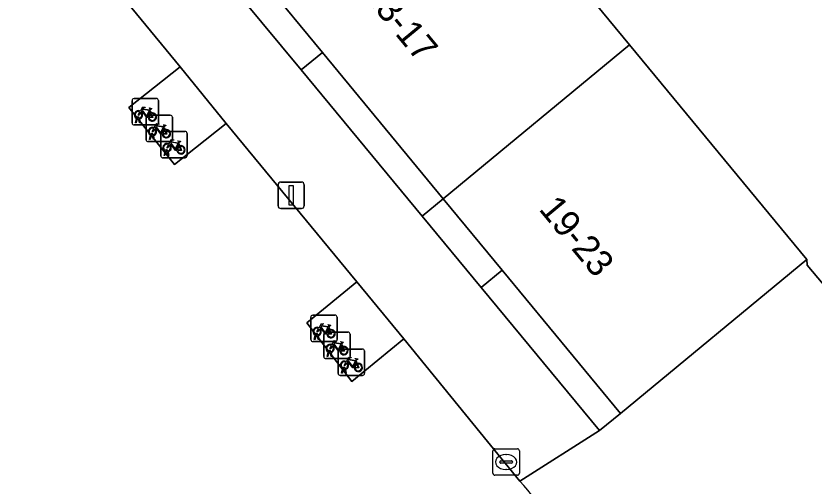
# Model space of a CAD drawing. Extents: x 162344 to 162869, y 381217 to 381818.
# Drawn here: x 162495.73 to 162525.97, y 381715.14 to 381732.95 of the extents above; entities that cross this region are included whole.
import ezdxf

# ---------------------------------------------------------------- set-up
doc = ezdxf.new("R2010")
doc.units = 0
for name, color, linetype in [('IMGEO_Erf', 7, 'Continuous'), ('IMGEO_Fietsenrek', 7, 'Continuous'), ('IMGEO_Groenvoorziening', 7, 'Continuous'), ('IMGEO_Kolk', 7, 'Continuous'), ('IMGEO_Lichtmast', 7, 'Continuous'), ('IMGEO_Pand', 7, 'Continuous'), ('IMGEO_Pand_nummerreeks', 7, 'Continuous'), ('IMGEO_Voetpad_open', 7, 'Continuous')]:
    doc.layers.add(name, color=color, linetype=linetype)

msp = doc.modelspace()

# ---------------------------------------------------------------- linework, layer by layer
at = {"layer": 'IMGEO_Erf'}
msp.add_lwpolyline([(162512.168, 381740.102), (162518.981, 381731.851), (162525.696, 381723.717), (162525.707, 381723.511), (162527.801, 381721.016), (162528.341, 381720.543), (162528.826, 381720.252), (162529.167, 381720.123), (162529.489, 381720.046), (162529.724, 381720.026)], dxfattribs=at)
at = {"layer": 'IMGEO_Fietsenrek'}
for p, q in [((162500.206, 381729.819), (162501.047, 381729.819)), ((162501.047, 381729.819), (162500.206, 381729.819)), ((162501.131, 381729.744), (162501.131, 381728.903)), ((162501.131, 381728.903), (162501.131, 381729.744)), ((162500.131, 381728.894), (162500.131, 381729.735)), ((162500.131, 381729.735), (162500.131, 381728.894)), ((162500.736, 381729.186), (162501.577, 381729.186)), ((162501.577, 381729.186), (162500.736, 381729.186)), ((162500.818, 381729.368), (162500.854, 381729.273)), ((162500.258, 381728.903), (162500.297, 381729.063)), ((162500.292, 381728.903), (162500.258, 381728.903)), ((162500.327, 381729.051), (162500.292, 381728.903)), ((162500.369, 381729.075), (162500.368, 381729.079)), ((162500.41, 381728.903), (162500.376, 381729.045)), ((162500.4, 381729.086), (162500.401, 381729.079)), ((162500.408, 381729.049), (162500.443, 381728.903)), ((162500.443, 381728.903), (162500.41, 381728.903)), ((162500.661, 381728.261), (162500.661, 381729.102)), ((162500.661, 381729.102), (162500.661, 381728.261)), ((162501.661, 381729.111), (162501.661, 381728.27)), ((162501.661, 381728.27), (162501.661, 381729.111)), ((162501.056, 381728.819), (162500.215, 381728.819)), ((162500.215, 381728.819), (162501.056, 381728.819)), ((162501.291, 381728.574), (162502.132, 381728.574)), ((162502.132, 381728.574), (162501.291, 381728.574)), ((162501.348, 381728.735), (162501.384, 381728.64)), ((162500.788, 381728.27), (162500.827, 381728.43)), ((162500.822, 381728.27), (162500.788, 381728.27)), ((162500.857, 381728.418), (162500.822, 381728.27)), ((162500.899, 381728.442), (162500.898, 381728.446)), ((162500.94, 381728.27), (162500.906, 381728.412)), ((162500.93, 381728.453), (162500.931, 381728.446)), ((162500.938, 381728.416), (162500.973, 381728.27)), ((162500.973, 381728.27), (162500.94, 381728.27)), ((162501.216, 381727.649), (162501.216, 381728.49)), ((162501.216, 381728.49), (162501.216, 381727.649)), ((162502.216, 381728.499), (162502.216, 381727.658)), ((162502.216, 381727.658), (162502.216, 381728.499)), ((162501.586, 381728.186), (162500.745, 381728.186)), ((162500.745, 381728.186), (162501.586, 381728.186)), ((162501.903, 381728.123), (162501.939, 381728.028)), ((162501.343, 381727.658), (162501.382, 381727.818)), ((162501.377, 381727.658), (162501.343, 381727.658)), ((162501.412, 381727.806), (162501.377, 381727.658)), ((162501.454, 381727.83), (162501.453, 381727.834)), ((162501.495, 381727.658), (162501.461, 381727.8)), ((162501.485, 381727.841), (162501.486, 381727.834)), ((162501.493, 381727.804), (162501.528, 381727.658)), ((162501.528, 381727.658), (162501.495, 381727.658)), ((162502.141, 381727.574), (162501.3, 381727.574)), ((162501.3, 381727.574), (162502.141, 381727.574)), ((162506.977, 381721.61), (162507.818, 381721.61)), ((162507.818, 381721.61), (162506.977, 381721.61)), ((162506.902, 381720.685), (162506.902, 381721.526)), ((162506.902, 381721.526), (162506.902, 381720.685)), ((162507.902, 381721.535), (162507.902, 381720.694)), ((162507.902, 381720.694), (162507.902, 381721.535)), ((162507.589, 381721.159), (162507.625, 381721.064)), ((162507.029, 381720.694), (162507.068, 381720.854)), ((162507.063, 381720.694), (162507.029, 381720.694)), ((162507.098, 381720.842), (162507.063, 381720.694)), ((162507.14, 381720.866), (162507.139, 381720.87)), ((162507.181, 381720.694), (162507.147, 381720.836)), ((162507.171, 381720.877), (162507.172, 381720.87)), ((162507.179, 381720.84), (162507.214, 381720.694)), ((162507.214, 381720.694), (162507.181, 381720.694)), ((162507.391, 381720.042), (162507.391, 381720.883)), ((162507.391, 381720.883), (162507.391, 381720.042)), ((162507.466, 381720.967), (162508.307, 381720.967)), ((162508.307, 381720.967), (162507.466, 381720.967)), ((162508.391, 381720.892), (162508.391, 381720.051)), ((162508.391, 381720.051), (162508.391, 381720.892)), ((162507.827, 381720.61), (162506.986, 381720.61)), ((162506.986, 381720.61), (162507.827, 381720.61)), ((162508.078, 381720.516), (162508.114, 381720.421)), ((162507.518, 381720.051), (162507.557, 381720.211)), ((162507.587, 381720.199), (162507.552, 381720.051)), ((162507.629, 381720.223), (162507.628, 381720.227)), ((162507.67, 381720.051), (162507.636, 381720.193)), ((162507.66, 381720.234), (162507.661, 381720.227)), ((162507.668, 381720.197), (162507.703, 381720.051)), ((162507.936, 381719.404), (162507.936, 381720.245)), ((162507.936, 381720.245), (162507.936, 381719.404)), ((162508.011, 381720.329), (162508.852, 381720.329)), ((162508.852, 381720.329), (162508.011, 381720.329)), ((162508.936, 381720.254), (162508.936, 381719.413)), ((162508.936, 381719.413), (162508.936, 381720.254)), ((162508.316, 381719.967), (162507.475, 381719.967)), ((162507.475, 381719.967), (162508.316, 381719.967)), ((162507.552, 381720.051), (162507.518, 381720.051)), ((162507.703, 381720.051), (162507.67, 381720.051)), ((162508.623, 381719.878), (162508.659, 381719.783)), ((162508.063, 381719.413), (162508.102, 381719.573)), ((162508.132, 381719.561), (162508.097, 381719.413)), ((162508.174, 381719.585), (162508.173, 381719.589)), ((162508.215, 381719.413), (162508.181, 381719.555)), ((162508.205, 381719.596), (162508.206, 381719.589)), ((162508.213, 381719.559), (162508.248, 381719.413)), ((162508.861, 381719.329), (162508.02, 381719.329)), ((162508.02, 381719.329), (162508.861, 381719.329)), ((162508.097, 381719.413), (162508.063, 381719.413)), ((162508.248, 381719.413), (162508.215, 381719.413))]:
    msp.add_line(p, q, dxfattribs=at)
for points in [[(162500.444, 381729.345), (162500.539, 381729.509), (162500.625, 381729.495), (162500.627, 381729.486), (162500.571, 381729.475), (162500.544, 381729.43), (162500.8, 381729.389)], [(162500.8, 381729.389), (162500.825, 381729.438), (162500.819, 381729.442), (162500.796, 381729.446), (162500.784, 381729.453), (162500.783, 381729.456), (162500.785, 381729.461), (162500.88, 381729.446), (162500.882, 381729.436), (162500.872, 381729.423), (162500.86, 381729.417), (162500.846, 381729.423), (162500.818, 381729.368)], [(162500.465, 381729.293), (162500.413, 381729.203), (162500.373, 381729.178), (162500.374, 381729.225), (162500.429, 381729.319)], [(162500.74, 381729.101), (162500.69, 381729.101), (162500.499, 381729.352), (162500.48, 381729.32)], [(162500.787, 381729.364), (162500.53, 381729.405), (162500.513, 381729.376), (162500.68, 381729.156), (162500.787, 381729.364)], [(162500.835, 381729.266), (162500.805, 381729.343), (162500.696, 381729.125), (162500.739, 381729.125)], [(162500.769, 381729.125), (162500.889, 381729.124), (162500.845, 381729.238)], [(162500.865, 381729.245), (162500.92, 381729.1), (162500.77, 381729.1)], [(162500.974, 381728.712), (162501.069, 381728.876), (162501.155, 381728.862), (162501.157, 381728.853), (162501.101, 381728.842), (162501.074, 381728.797), (162501.33, 381728.756)], [(162500.995, 381728.66), (162500.943, 381728.57), (162500.903, 381728.545), (162500.904, 381728.592), (162500.959, 381728.686)], [(162501.27, 381728.468), (162501.22, 381728.468), (162501.029, 381728.719), (162501.01, 381728.687)], [(162501.317, 381728.731), (162501.06, 381728.772), (162501.043, 381728.743), (162501.21, 381728.523), (162501.317, 381728.731)], [(162501.365, 381728.633), (162501.335, 381728.71), (162501.226, 381728.492), (162501.269, 381728.492)], [(162501.299, 381728.492), (162501.419, 381728.491), (162501.375, 381728.605)], [(162501.395, 381728.612), (162501.45, 381728.467), (162501.3, 381728.467)], [(162501.33, 381728.756), (162501.355, 381728.805), (162501.349, 381728.809), (162501.326, 381728.813), (162501.314, 381728.82), (162501.313, 381728.823), (162501.315, 381728.828), (162501.41, 381728.813), (162501.412, 381728.803), (162501.402, 381728.79), (162501.39, 381728.784), (162501.376, 381728.79), (162501.348, 381728.735)], [(162501.529, 381728.1), (162501.624, 381728.264), (162501.71, 381728.25), (162501.712, 381728.241), (162501.656, 381728.23), (162501.629, 381728.185), (162501.885, 381728.144)], [(162501.55, 381728.048), (162501.498, 381727.958), (162501.458, 381727.933), (162501.459, 381727.98), (162501.514, 381728.074)], [(162501.825, 381727.856), (162501.775, 381727.856), (162501.584, 381728.107), (162501.565, 381728.075)], [(162501.872, 381728.119), (162501.615, 381728.16), (162501.598, 381728.131), (162501.765, 381727.911), (162501.872, 381728.119)], [(162501.92, 381728.021), (162501.89, 381728.098), (162501.781, 381727.88), (162501.824, 381727.88)], [(162501.854, 381727.88), (162501.974, 381727.879), (162501.93, 381727.993)], [(162501.95, 381728), (162502.005, 381727.855), (162501.855, 381727.855)], [(162501.885, 381728.144), (162501.91, 381728.193), (162501.904, 381728.197), (162501.881, 381728.201), (162501.869, 381728.208), (162501.868, 381728.211), (162501.87, 381728.216), (162501.965, 381728.201), (162501.967, 381728.191), (162501.957, 381728.178), (162501.945, 381728.172), (162501.931, 381728.178), (162501.903, 381728.123)], [(162507.215, 381721.136), (162507.31, 381721.3), (162507.396, 381721.286), (162507.398, 381721.277), (162507.342, 381721.266), (162507.315, 381721.221), (162507.571, 381721.18)], [(162507.236, 381721.084), (162507.184, 381720.994), (162507.144, 381720.969), (162507.145, 381721.016), (162507.2, 381721.11)], [(162507.511, 381720.892), (162507.461, 381720.892), (162507.27, 381721.143), (162507.251, 381721.111)], [(162507.558, 381721.155), (162507.301, 381721.196), (162507.284, 381721.167), (162507.451, 381720.947), (162507.558, 381721.155)], [(162507.606, 381721.057), (162507.576, 381721.134), (162507.467, 381720.916), (162507.51, 381720.916)], [(162507.54, 381720.916), (162507.66, 381720.915), (162507.616, 381721.029)], [(162507.636, 381721.036), (162507.691, 381720.891), (162507.541, 381720.891)], [(162507.571, 381721.18), (162507.596, 381721.229), (162507.59, 381721.233), (162507.567, 381721.237), (162507.555, 381721.244), (162507.554, 381721.247), (162507.556, 381721.252), (162507.651, 381721.237), (162507.653, 381721.227), (162507.643, 381721.214), (162507.631, 381721.208), (162507.617, 381721.214), (162507.589, 381721.159)], [(162507.725, 381720.441), (162507.673, 381720.351), (162507.633, 381720.326), (162507.634, 381720.373), (162507.689, 381720.467)], [(162507.704, 381720.493), (162507.799, 381720.657), (162507.885, 381720.643), (162507.887, 381720.634), (162507.831, 381720.623), (162507.804, 381720.578), (162508.06, 381720.537)], [(162508, 381720.249), (162507.95, 381720.249), (162507.759, 381720.5), (162507.74, 381720.468)], [(162508.047, 381720.512), (162507.79, 381720.553), (162507.773, 381720.524), (162507.94, 381720.304), (162508.047, 381720.512)], [(162508.095, 381720.414), (162508.065, 381720.491), (162507.956, 381720.273), (162507.999, 381720.273)], [(162508.029, 381720.273), (162508.149, 381720.272), (162508.105, 381720.386)], [(162508.125, 381720.393), (162508.18, 381720.248), (162508.03, 381720.248)], [(162508.06, 381720.537), (162508.085, 381720.586), (162508.079, 381720.59), (162508.056, 381720.594), (162508.044, 381720.601), (162508.043, 381720.604), (162508.045, 381720.609), (162508.14, 381720.594), (162508.142, 381720.584), (162508.132, 381720.571), (162508.12, 381720.565), (162508.106, 381720.571), (162508.078, 381720.516)], [(162508.27, 381719.803), (162508.218, 381719.713), (162508.178, 381719.688), (162508.179, 381719.735), (162508.234, 381719.829)], [(162508.249, 381719.855), (162508.344, 381720.019), (162508.43, 381720.005), (162508.432, 381719.996), (162508.376, 381719.985), (162508.349, 381719.94), (162508.605, 381719.899)], [(162508.545, 381719.611), (162508.495, 381719.611), (162508.304, 381719.862), (162508.285, 381719.83)], [(162508.592, 381719.874), (162508.335, 381719.915), (162508.318, 381719.886), (162508.485, 381719.666), (162508.592, 381719.874)], [(162508.64, 381719.776), (162508.61, 381719.853), (162508.501, 381719.635), (162508.544, 381719.635)], [(162508.605, 381719.899), (162508.63, 381719.948), (162508.624, 381719.952), (162508.601, 381719.956), (162508.589, 381719.963), (162508.588, 381719.966), (162508.59, 381719.971), (162508.685, 381719.956), (162508.687, 381719.946), (162508.677, 381719.933), (162508.665, 381719.927), (162508.651, 381719.933), (162508.623, 381719.878)], [(162508.574, 381719.635), (162508.694, 381719.634), (162508.65, 381719.748)], [(162508.67, 381719.755), (162508.725, 381719.61), (162508.575, 381719.61)]]:
    msp.add_lwpolyline(points, dxfattribs=at)
for centre, radius, start, end in [((162500.209, 381729.741), 0.0779, 92.4484, 184.2845), ((162500.209, 381729.741), 0.0779, 92.4484, 184.2845), ((162501.053, 381729.741), 0.0779, 2.4484, 94.2845), ((162501.053, 381729.741), 0.0779, 2.4484, 94.2845), ((162500.371, 381729.204), 0.159, 62.6766, 242.1369), ((162500.371, 381729.204), 0.129, 63.3192, 238.903), ((162500.371, 381729.204), 0.129, 283.6043, 43.4302), ((162500.371, 381729.204), 0.159, 283.5766, 46.6042), ((162500.739, 381729.108), 0.0779, 92.4484, 184.2845), ((162500.739, 381729.108), 0.0779, 92.4484, 184.2845), ((162500.898, 381729.12), 0.159, 113.3408, 178.3217), ((162500.898, 381729.12), 0.159, 187.0065, 105.7708), ((162500.898, 381729.12), 0.129, 113.923, 177.9556), ((162500.898, 381729.12), 0.129, 188.6715, 104.5883), ((162501.583, 381729.108), 0.0779, 2.4484, 94.2845), ((162501.583, 381729.108), 0.0779, 2.4484, 94.2845), ((162500.209, 381728.897), 0.0779, 182.4484, 274.2845), ((162500.209, 381728.897), 0.0779, 182.4484, 274.2845), ((162500.351, 381729.075), 0.0499, 12.8025, 158.6934), ((162500.371, 381729.204), 0.159, 253.9967, 271.7867), ((162500.351, 381729.075), 0.0174, 12.8025, 163.4502), ((162500.371, 381729.204), 0.129, 253.415, 269.0204), ((162501.053, 381728.897), 0.0779, 272.4484, 4.2845), ((162501.053, 381728.897), 0.0779, 272.4484, 4.2845), ((162500.901, 381728.571), 0.159, 62.6766, 242.1369), ((162500.901, 381728.571), 0.129, 63.3192, 238.903), ((162500.901, 381728.571), 0.129, 283.6043, 43.4302), ((162500.901, 381728.571), 0.159, 283.5766, 46.6042), ((162501.294, 381728.496), 0.0779, 92.4484, 184.2845), ((162501.294, 381728.496), 0.0779, 92.4484, 184.2845), ((162501.428, 381728.487), 0.159, 113.3408, 178.3217), ((162501.428, 381728.487), 0.159, 187.0065, 105.7708), ((162501.428, 381728.487), 0.129, 113.923, 177.9556), ((162501.428, 381728.487), 0.129, 188.6715, 104.5883), ((162502.138, 381728.496), 0.0779, 2.4484, 94.2845), ((162502.138, 381728.496), 0.0779, 2.4484, 94.2845), ((162500.739, 381728.264), 0.0779, 182.4484, 274.2845), ((162500.739, 381728.264), 0.0779, 182.4484, 274.2845), ((162500.881, 381728.442), 0.0499, 12.8025, 158.6934), ((162500.901, 381728.571), 0.159, 253.9967, 271.7867), ((162500.881, 381728.442), 0.0174, 12.8025, 163.4502), ((162500.901, 381728.571), 0.129, 253.415, 269.0204), ((162501.583, 381728.264), 0.0779, 272.4484, 4.2845), ((162501.583, 381728.264), 0.0779, 272.4484, 4.2845), ((162501.456, 381727.959), 0.159, 62.6766, 242.1369), ((162501.456, 381727.959), 0.129, 63.3192, 238.903), ((162501.456, 381727.959), 0.129, 283.6043, 43.4302), ((162501.456, 381727.959), 0.159, 283.5766, 46.6042), ((162501.983, 381727.875), 0.159, 113.3408, 178.3217), ((162501.983, 381727.875), 0.159, 187.0065, 105.7708), ((162501.983, 381727.875), 0.129, 113.923, 177.9556), ((162501.983, 381727.875), 0.129, 188.6715, 104.5883), ((162501.294, 381727.652), 0.0779, 182.4484, 274.2845), ((162501.294, 381727.652), 0.0779, 182.4484, 274.2845), ((162501.436, 381727.83), 0.0499, 12.8025, 158.6934), ((162501.456, 381727.959), 0.159, 253.9967, 271.7867), ((162501.436, 381727.83), 0.0174, 12.8025, 163.4502), ((162501.456, 381727.959), 0.129, 253.415, 269.0204), ((162502.138, 381727.652), 0.0779, 272.4484, 4.2845), ((162502.138, 381727.652), 0.0779, 272.4484, 4.2845), ((162506.98, 381721.532), 0.0779, 92.4484, 184.2845), ((162506.98, 381721.532), 0.0779, 92.4484, 184.2845), ((162507.824, 381721.532), 0.0779, 2.4484, 94.2845), ((162507.824, 381721.532), 0.0779, 2.4484, 94.2845), ((162507.142, 381720.995), 0.159, 62.6766, 242.1369), ((162507.142, 381720.995), 0.129, 63.3192, 238.903), ((162507.142, 381720.995), 0.129, 283.6043, 43.4302), ((162507.142, 381720.995), 0.159, 283.5766, 46.6042), ((162507.669, 381720.911), 0.159, 113.3408, 178.3217), ((162507.669, 381720.911), 0.159, 187.0065, 105.7708), ((162507.669, 381720.911), 0.129, 113.923, 177.9556), ((162507.669, 381720.911), 0.129, 188.6715, 104.5883), ((162506.98, 381720.688), 0.0779, 182.4484, 274.2845), ((162506.98, 381720.688), 0.0779, 182.4484, 274.2845), ((162507.122, 381720.866), 0.0499, 12.8025, 158.6934), ((162507.142, 381720.995), 0.159, 253.9967, 271.7867), ((162507.122, 381720.866), 0.0174, 12.8025, 163.4502), ((162507.142, 381720.995), 0.129, 253.415, 269.0204), ((162507.469, 381720.889), 0.0779, 92.4484, 184.2845), ((162507.469, 381720.889), 0.0779, 92.4484, 184.2845), ((162507.824, 381720.688), 0.0779, 272.4484, 4.2845), ((162507.824, 381720.688), 0.0779, 272.4484, 4.2845), ((162508.313, 381720.889), 0.0779, 2.4484, 94.2845), ((162508.313, 381720.889), 0.0779, 2.4484, 94.2845), ((162507.631, 381720.352), 0.159, 62.6766, 242.1369), ((162507.631, 381720.352), 0.129, 63.3192, 238.903), ((162507.631, 381720.352), 0.129, 283.6043, 43.4302), ((162507.631, 381720.352), 0.159, 283.5766, 46.6042), ((162508.158, 381720.268), 0.159, 113.3408, 178.3217), ((162508.158, 381720.268), 0.159, 187.0065, 105.7708), ((162508.158, 381720.268), 0.129, 113.923, 177.9556), ((162508.158, 381720.268), 0.129, 188.6715, 104.5883), ((162507.611, 381720.223), 0.0499, 12.8025, 158.6934), ((162507.631, 381720.352), 0.159, 253.9967, 271.7867), ((162507.611, 381720.223), 0.0174, 12.8025, 163.4502), ((162507.631, 381720.352), 0.129, 253.415, 269.0204), ((162508.014, 381720.251), 0.0779, 92.4484, 184.2845), ((162508.014, 381720.251), 0.0779, 92.4484, 184.2845), ((162508.858, 381720.251), 0.0779, 2.4484, 94.2845), ((162508.858, 381720.251), 0.0779, 2.4484, 94.2845), ((162507.469, 381720.045), 0.0779, 182.4484, 274.2845), ((162507.469, 381720.045), 0.0779, 182.4484, 274.2845), ((162508.176, 381719.714), 0.159, 62.6766, 242.1369), ((162508.176, 381719.714), 0.129, 63.3192, 238.903), ((162508.176, 381719.714), 0.129, 283.6043, 43.4302), ((162508.176, 381719.714), 0.159, 283.5766, 46.6042), ((162508.313, 381720.045), 0.0779, 272.4484, 4.2845), ((162508.313, 381720.045), 0.0779, 272.4484, 4.2845), ((162508.703, 381719.63), 0.159, 113.3408, 178.3217), ((162508.703, 381719.63), 0.159, 187.0065, 105.7708), ((162508.703, 381719.63), 0.129, 188.6715, 104.5883), ((162508.156, 381719.585), 0.0499, 12.8025, 158.6934), ((162508.176, 381719.714), 0.159, 253.9967, 271.7867), ((162508.156, 381719.585), 0.0174, 12.8025, 163.4502), ((162508.176, 381719.714), 0.129, 253.415, 269.0204), ((162508.703, 381719.63), 0.129, 113.923, 177.9556), ((162508.014, 381719.407), 0.0779, 182.4484, 274.2845), ((162508.014, 381719.407), 0.0779, 182.4484, 274.2845), ((162508.858, 381719.407), 0.0779, 272.4484, 4.2845), ((162508.858, 381719.407), 0.0779, 272.4484, 4.2845)]:
    msp.add_arc(centre, radius, start, end, dxfattribs=at)
at = {"layer": 'IMGEO_Groenvoorziening'}
msp.add_lwpolyline([(162514.818, 381715.325), (162510.426, 381720.718), (162508.452, 381719.099), (162506.749, 381721.315), (162508.651, 381722.872), (162503.699, 381728.875), (162501.738, 381727.316), (162500.005, 381729.485), (162501.958, 381731.025), (162496.987, 381737.052)], dxfattribs=at)
for points in [[(162507.34, 381731.568), (162506.542, 381730.909), (162511.123, 381725.368), (162511.916, 381726.022)], [(162514.15, 381723.315), (162513.359, 381722.662), (162517.837, 381717.246), (162518.63, 381717.886)]]:
    msp.add_lwpolyline(points, close=True, dxfattribs=at)
msp.add_arc((162511.737, 381712.226), 4.37, 310.0727, 45.1636, dxfattribs=at)
at = {"layer": 'IMGEO_Kolk'}
for p, q in [((162513.802, 381715.621), (162513.802, 381716.473)), ((162513.877, 381716.547), (162514.729, 381716.547)), ((162514.803, 381716.473), (162514.803, 381715.621)), ((162514.29, 381716.327), (162514.315, 381716.327)), ((162514.061, 381716.041), (162514.061, 381716.053)), ((162514.499, 381716.004), (162514.101, 381716.004)), ((162514.104, 381716.09), (162514.502, 381716.09)), ((162514.545, 381716.053), (162514.545, 381716.041)), ((162514.729, 381715.547), (162513.877, 381715.547)), ((162514.313, 381715.767), (162514.288, 381715.767))]:
    msp.add_line(p, q, dxfattribs=at)
for points in [[(162513.802, 381715.621), (162513.802, 381716.473)], [(162513.877, 381716.547), (162514.729, 381716.547)], [(162514.803, 381716.473), (162514.803, 381715.621)], [(162514.729, 381715.547), (162513.877, 381715.547)]]:
    msp.add_lwpolyline(points, dxfattribs=at)
for centre, radius, start, end in [((162513.879, 381716.471), 0.0765, 91.552, 178.448), ((162513.879, 381716.471), 0.0765, 91.552, 178.448), ((162514.727, 381716.471), 0.0765, 1.552, 88.448), ((162514.727, 381716.471), 0.0765, 1.552, 88.448), ((162514.101, 381716.05), 0.0403, 85.8775, 175.7526), ((162514.098, 381716.04), 0.0366, 178.938, 274.7102), ((162514.502, 381716.047), 0.043, 264.8664, 352.4533), ((162514.506, 381716.052), 0.0386, 1.7309, 96.639), ((162513.879, 381715.623), 0.0765, 181.552, 268.448), ((162513.879, 381715.623), 0.0765, 181.552, 268.448), ((162514.727, 381715.623), 0.0765, 271.552, 358.448), ((162514.727, 381715.623), 0.0765, 271.552, 358.448)]:
    msp.add_arc(centre, radius, start, end, dxfattribs=at)
for centre, major_axis, ratio, start_param, end_param in [((162514.289, 381716.047), (-0.387, 0.002), 0.722429, 4.712389, 7.853982), ((162514.314, 381716.047), (-0.39, 0.002), 0.717154, 1.570796, 4.712389)]:
    msp.add_ellipse(centre, major_axis=major_axis, ratio=ratio, start_param=start_param, end_param=end_param, dxfattribs=at)
at = {"layer": 'IMGEO_Lichtmast'}
for p, q in [((162505.662, 381725.754), (162505.662, 381726.554)), ((162505.662, 381726.554), (162505.662, 381725.754)), ((162505.762, 381726.654), (162506.552, 381726.654)), ((162506.552, 381726.654), (162505.762, 381726.654)), ((162506.652, 381726.554), (162506.652, 381725.754)), ((162506.652, 381725.754), (162506.652, 381726.554)), ((162506.552, 381725.654), (162505.762, 381725.654)), ((162505.762, 381725.654), (162506.552, 381725.654))]:
    msp.add_line(p, q, dxfattribs=at)
msp.add_lwpolyline([(162506.082, 381726.529), (162506.232, 381726.529), (162506.232, 381725.779), (162506.082, 381725.779), (162506.082, 381726.529)], dxfattribs=at)
for centre, start, end in [((162505.762, 381726.554), 90, 180), ((162505.762, 381726.554), 90, 180), ((162506.552, 381726.554), 0, 90), ((162506.552, 381726.554), 360, 90), ((162505.762, 381725.754), 180, 270), ((162505.762, 381725.754), 180, 270), ((162506.552, 381725.754), 270, 0), ((162506.552, 381725.754), 270, 0)]:
    msp.add_arc(centre, 0.1, start, end, dxfattribs=at)
at = {"layer": 'IMGEO_Pand'}
for points in [[(162512.168, 381740.102), (162505.106, 381734.275), (162507.34, 381731.568), (162511.916, 381726.022), (162518.981, 381731.851)], [(162518.981, 381731.851), (162511.916, 381726.022), (162514.15, 381723.315), (162518.63, 381717.886), (162525.696, 381723.717)]]:
    msp.add_lwpolyline(points, close=True, dxfattribs=at)
at = {"layer": 'IMGEO_Voetpad_open'}
for points in [[(162499.724, 381739.156), (162497.488, 381741.861), (162492.906, 381747.402), (162490.67, 381750.108), (162483.924, 381758.308), (162483.032, 381759.392), (162480.048, 381763.094), (162477.365, 381760.866), (162486.667, 381749.611), (162488.397, 381747.426), (162495.209, 381739.256), (162496.987, 381737.052), (162501.958, 381731.025), (162503.699, 381728.875), (162508.651, 381722.872), (162510.426, 381720.718), (162514.818, 381715.325), (162517.837, 381717.246), (162513.359, 381722.662), (162511.123, 381725.368), (162506.542, 381730.909), (162504.305, 381733.614)], [(162505.106, 381734.275), (162504.305, 381733.614), (162506.542, 381730.909), (162507.34, 381731.568)], [(162501.958, 381731.025), (162500.005, 381729.485), (162501.738, 381727.316), (162503.699, 381728.875)], [(162511.916, 381726.022), (162511.123, 381725.368), (162513.359, 381722.662), (162514.15, 381723.315)], [(162508.651, 381722.872), (162506.749, 381721.315), (162508.452, 381719.099), (162510.426, 381720.718)]]:
    msp.add_lwpolyline(points, close=True, dxfattribs=at)
msp.add_lwpolyline([(162529.724, 381720.026), (162529.489, 381720.046), (162529.167, 381720.123), (162528.826, 381720.252), (162528.341, 381720.543), (162527.801, 381721.016), (162525.707, 381723.511), (162525.696, 381723.717), (162518.63, 381717.886), (162517.837, 381717.246), (162514.818, 381715.325)], dxfattribs=at)
msp.add_arc((162511.737, 381712.226), 4.37, 310.0727, 45.1636, dxfattribs=at)

# ---------------------------------------------------------------- texts
at = {"layer": 'IMGEO_Pand_nummerreeks'}
for s, rotation, p in [('13-17', 309.5396, (162508.835, 381733.759)), ('19-23', 309.6485, (162515.511, 381725.618))]:
    msp.add_text(s, height=1, rotation=rotation, dxfattribs=at).set_placement(p)

doc.saveas('drawing.dxf')
